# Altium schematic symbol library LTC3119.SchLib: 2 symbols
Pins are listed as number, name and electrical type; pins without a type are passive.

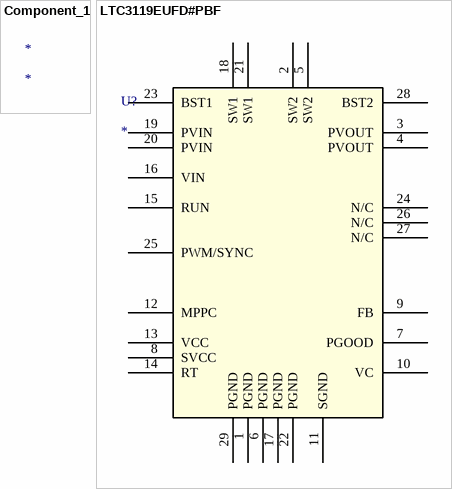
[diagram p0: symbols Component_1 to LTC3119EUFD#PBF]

## Component_1
designator *

## LTC3119EUFD#PBF
designator U?
No Description Available
footprint QFN28_UFD
pins: 1 PGND, 2 SW2, 3 PVOUT, 4 PVOUT, 5 SW2, 6 PGND, 7 PGOOD, 8 SVCC, 9 FB, 10 VC, 11 SGND, 12 MPPC, 13 VCC, 14 RT, 15 RUN, 16 VIN, 17 PGND, 18 SW1, 19 PVIN, 20 PVIN, 21 SW1, 22 PGND, 23 BST1, 24 N/C, 25 PWM/SYNC, 26 N/C, 27 N/C, 28 BST2, 29 PGND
